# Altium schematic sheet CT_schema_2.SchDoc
size 362 x 192 mm
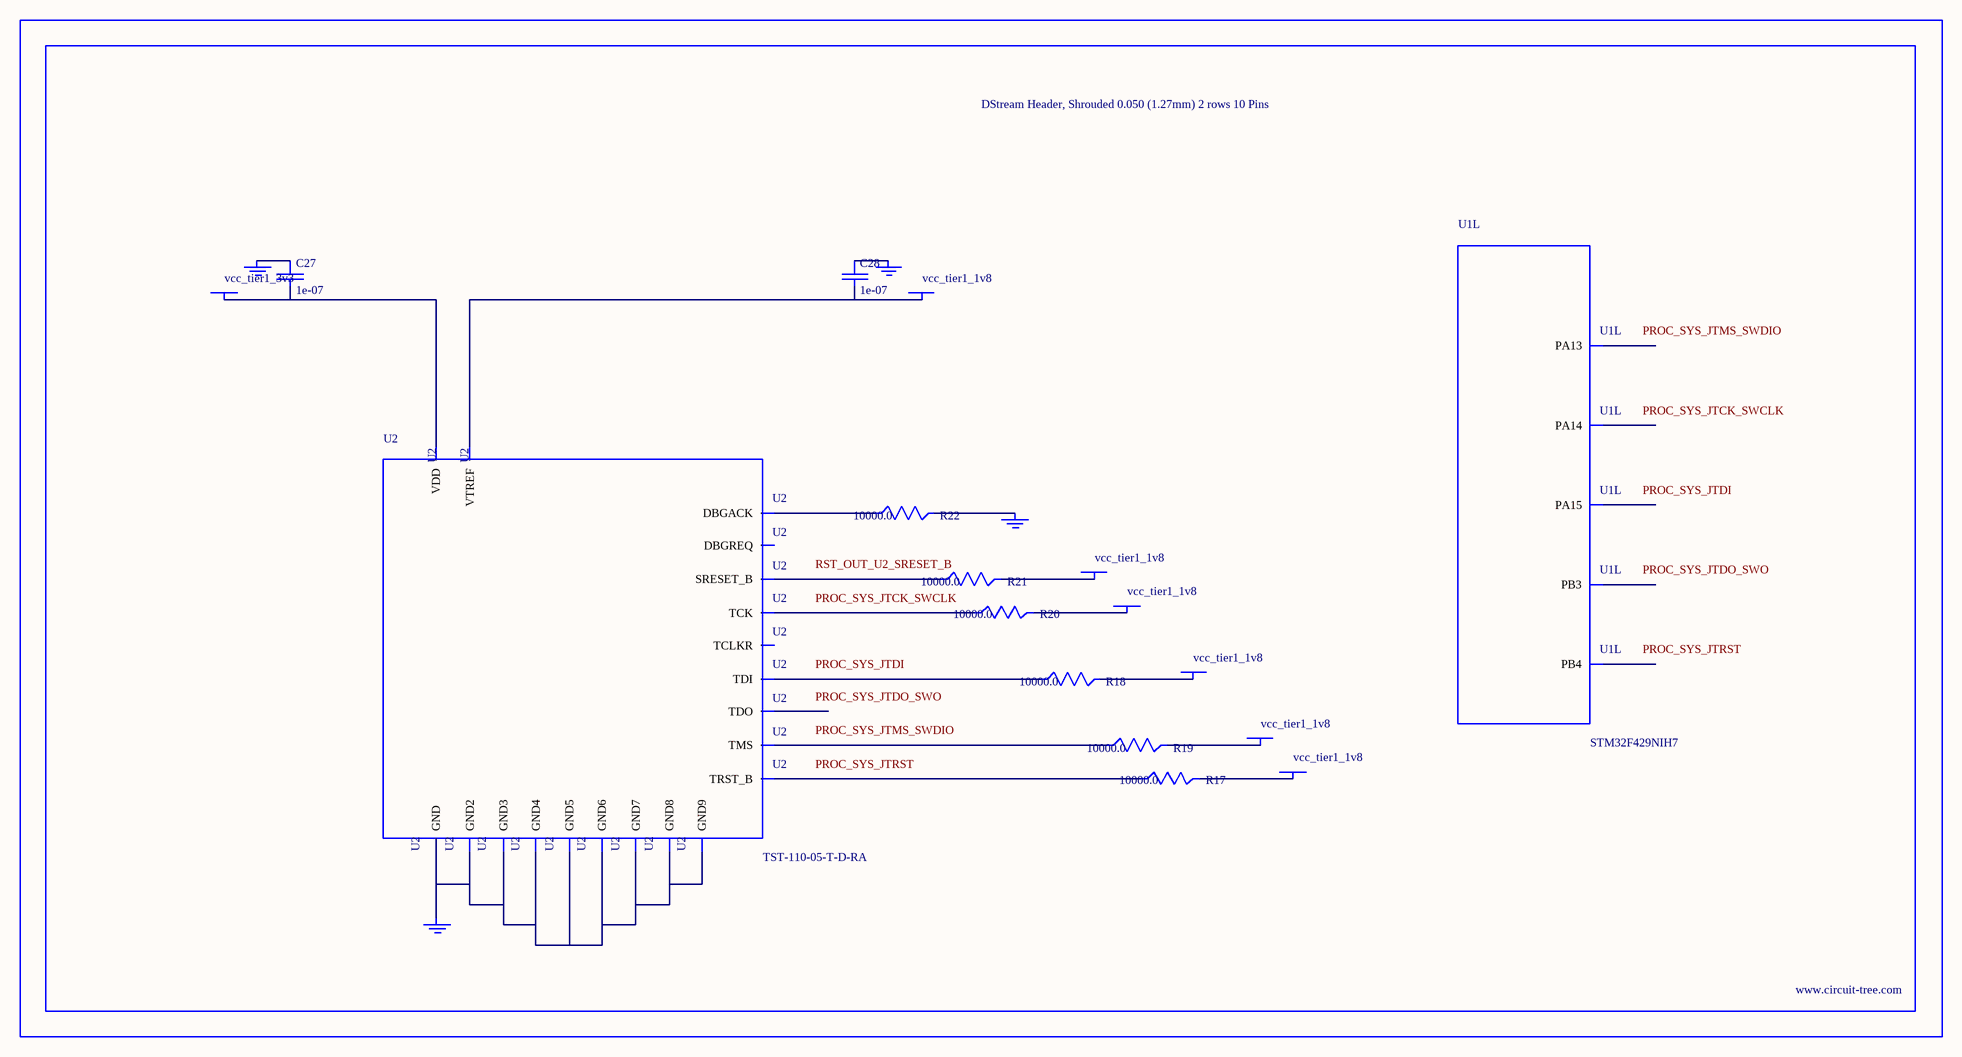
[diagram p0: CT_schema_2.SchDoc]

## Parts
BORDER1  (no value)
C27  1e-07  [C0402]
C28  1e-07  [C0402]
GND_INSTANCE_1_0  (no value)
GND_INSTANCE_1_1  (no value)
GND_INSTANCE_1_2  (no value)
GND_INSTANCE_1_3  (no value)
POWER_INSTANCE_1_0  vcc_tier1_1v8
POWER_INSTANCE_1_1  vcc_tier1_3v3
POWER_INSTANCE_1_2  vcc_tier1_1v8
POWER_INSTANCE_1_3  vcc_tier1_1v8
POWER_INSTANCE_1_4  vcc_tier1_1v8
POWER_INSTANCE_1_5  vcc_tier1_1v8
POWER_INSTANCE_1_6  vcc_tier1_1v8
R17  10000.0  [R0603]
R18  10000.0  [R0603]
R19  10000.0  [R0603]
R20  10000.0  [R0603]
R21  10000.0  [R0603]
R22  10000.0  [R0603]
U1  STM32F429NIH7  [TFBGA216]  (part L of 16)
U2  TST-110-05-T-D-RA  [TST-110-05-T-D-RA]

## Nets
NetC27_1: C27.1 GND_INSTANCE_1_1.0(GND)
NetC27_2: C27.2 POWER_INSTANCE_1_1.0(PWR) U2.2(VDD)
NetC28_1: C28.1 GND_INSTANCE_1_0.0(GND)
NetC28_2: C28.2 POWER_INSTANCE_1_0.0(PWR) U2.1(VTREF)
NetGND_INSTANCE_1_2_0: GND_INSTANCE_1_2.0(GND) R22.2
NetGND_INSTANCE_1_3_0: GND_INSTANCE_1_3.0(GND) U2.4(GND) U2.6(GND2) U2.8(GND3) U2.10(GND4) U2.12(GND5) U2.14(GND6) U2.16(GND7) U2.18(GND8) U2.20(GND9)
NetPOWER_INSTANCE_1_2_0: POWER_INSTANCE_1_2.0(PWR) R17.2
NetPOWER_INSTANCE_1_3_0: POWER_INSTANCE_1_3.0(PWR) R18.2
NetPOWER_INSTANCE_1_4_0: POWER_INSTANCE_1_4.0(PWR) R19.2
NetPOWER_INSTANCE_1_5_0: POWER_INSTANCE_1_5.0(PWR) R20.2
NetPOWER_INSTANCE_1_6_0: POWER_INSTANCE_1_6.0(PWR) R21.2
NetR17_1: R17.1 U2.3(TRST_B)
NetR18_1: R18.1 U2.5(TDI)
NetR19_1: R19.1 U2.7(TMS)
NetR20_1: R20.1 U2.9(TCK)
NetR21_1: R21.1 U2.15(SRESET_B)
NetR22_1: R22.1 U2.19(DBGACK)

Not connected (* = marked no-connect by the designer): U1 A9(PB4) A10(PB3) A13(PA15) A14(PA14) A15(PA13); U2 11(TCLKR) 13(TDO) 17(DBGREQ)

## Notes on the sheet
- Labels drawn without touching a wire or pin: PROC_SYS_JTCK_SWCLK, PROC_SYS_JTDI, PROC_SYS_JTDO_SWO, PROC_SYS_JTMS_SWDIO, PROC_SYS_JTRST, RST_OUT_U2_SRESET_B

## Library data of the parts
BORDER1 = BORDER_PAGE1
C27 C28 = C0402C104K3RACTU
GND_INSTANCE_1_0-GND_INSTANCE_1_3 = GND
POWER_INSTANCE_1_0-POWER_INSTANCE_1_6 = PWR
R17-R22 = RC0603JR-0710KL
